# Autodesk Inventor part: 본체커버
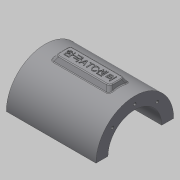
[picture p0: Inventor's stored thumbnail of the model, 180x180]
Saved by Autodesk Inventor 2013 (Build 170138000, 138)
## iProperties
Created: 2015-12
Part Number: 본체커버
Material: 일반
Document SubType Name: Modeling
Designer: mduedu
Density: 2.71 g/cm^3
Mass: 199.348 g
Surface Area: 200.806 cm^2
Volume: 73.5601 cm^3
Author: mduedu
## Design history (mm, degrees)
sketch "스케치1"
  geometry: L1 (45, 40)-(-45, 40); L2 (-45, 40)-(-45, -40); L3 (-45, -40)-(45, -40); L4 (45, -40)-(45, 40); L5 (45, 40)-(-45, -40); L6 (-45, 40)-(45, -40); 1 further point
  constraints: 12 end point, 2 midpoint, 2 parallel, 1 horizontal, 1 perpendicular
  dimensions: "d0" = 90 distance of L2.end L3.end; "d2" = 80 distance of L1.end L2.end
extrude "돌출1" new body sketch "스케치1" distance "d3" = 10; taper "d4" = 0 deg
sketch "스케치2"
  geometry: L1 (0, 40)-(0, -40) reference; C1 r 32.5 at (80, 0); 1 further point
  constraints: 1 centre point
  dimensions: "d5" = 65 diameter of C1; "d6" = 80 distance from line of C1.centre L1
extrude "돌출2" join sketch "스케치2" stored distance "d7" = 75; taper "d8" = 0 deg
sketch "스케치3"
  geometry: L1 (-27.5, -20)-(27.5, -20); L2 (27.5, -20)-(27.5, 20); L3 (27.5, 20)-(-27.5, 20); L4 (-27.5, 20)-(-27.5, -20); L5 (-27.5, -20)-(27.5, 20); L6 (27.5, -20)-(-27.5, 20); 1 further point
  constraints: 12 end point, 2 midpoint, 2 parallel, 1 horizontal, 1 perpendicular
  dimensions: "d9" = 55 distance of L2.end L3.end; "d11" = 40 distance of L1.end L2.end
extrude "돌출3" new body sketch "스케치3" stored distance "d12" = 75; taper "d13" = 0 deg
fillet "모깎기1"
fillet "모깎기2"
feature "결합1"
  node "솔리드2"
fillet "모깎기3" dims "d14" = 10
sketch "스케치4"
  geometry: L1 (-37.5, 47.5)-(37.5, 47.5) reference; L2 (35, 10)-(45, 10) reference; L3 (32.5, 47.5)-(40, 10); L4 (37.5, 47.5)-(37.5, 112.5) reference; L5 (45, 10)-(45, 0) reference; 1 further point
  constraints: 2 end point, 1 midpoint, 1 point on line
  dimensions: "d15" = 5 distance from line of L3.start L4; "d16" = 5 distance from line of L3.end L5
sketch "스케치5"
  geometry: L1 (10, 40)-(10, 30) reference; L2 (10, 35)-(56.569, 22.522); L3 (0, 40)-(10, 40) reference; 2 further points
  constraints: 2 end point, 1 midpoint, 2 other
  dimensions: "d17" = 5 distance from line of L2.start L3; "d18" = 15 deg angle of L2 L3
feature "리브1" dims "d19" = 1, "d20" = 6, "d21" = 0, "d22" = 0, "d23" = 1, "d24" = 1
feature "리브2" dims "d25" = 1, "d26" = 6, "d27" = 0, "d28" = 0, "d29" = 1, "d30" = 1
fillet "모깎기4" dims "d31" = 2
fillet "모깎기5" dims "d32" = 2
fillet "모깎기6" dims "d33" = 2
sketch "스케치6"
  geometry: A1 r 10 centre (-35, 30) between (-35, 40) and (-45, 30) reference; A2 r 10 centre (35, 30) between (45, 30) and (35, 40) reference; A3 r 10 centre (35, -30) between (35, -40) and (45, -30) reference; A4 r 10 centre (-35, -30) between (-45, -30) and (-35, -40) reference; 5 further points
  constraints: 4 coincident
hole "구멍1" sketch "스케치6" at (-35, 30), (35, 30), (35, -30), (-35, -30) diameter "d34" = 7; stored, may be unused: countersink angle "d38" = 90 deg, drill point angle "d40" = 118 deg; dims "d35" = 6, "d36" = 12, "d37" = 3, "d39" = 8
fillet "모깎기7" dims "d41" = 2
hole "구멍2" diameter "d44" = 45; stored, may be unused: countersink angle "d48" = 90 deg, drill point angle "d50" = 118 deg; dims "d42" = 10, "d43" = 10, "d45" = 6, "d46" = 4, "d47" = 2, "d49" = 8
sketch "스케치7" dims "d52" = 26.5
  geometry: L1 (0, 0)-(32.5, 0); L2 (0, 0)-(0, 32.5); A1 r 32.5 centre (0, 0) between (32.5, 0) and (0, 32.5) reference; 3 further points
  constraints: 4 end point, 2 point on circle, 1 coincident, 1 horizontal, 1 point on line, 1 vertical alignment, 2 other
  dimensions: "d51" = 90 deg angle of L2 L1
hole "구멍3" sketch "스케치7" at (0, 26.5) diameter "d54" = 2.459; stored, may be unused: countersink angle "d58" = 90 deg, drill point angle "d60" = 118 deg; dims "d55" = 8, "d56" = 4, "d57" = 2, "d59" = 10
sketch "스케치13"
  geometry: L1 (-45, 80)-(105, 80); L2 (105, 80)-(105, -30); L3 (105, -30)-(-45, -30); L4 (-45, -30)-(-45, 80); L5 (0, 0)-(60, 0) reference; C1 r 32.5 at (30, 80) reference; 1 further point
  constraints: 8 end point, 2 parallel, 1 coincident, 1 horizontal, 1 midpoint, 1 perpendicular
  dimensions: "d99" = 30 distance between parallel lines of L3 L5; "d126" = 150 distance between parallel lines of L2 L4
extrude "돌출8" cut sketch "스케치13" stored distance "d97" = 10; taper "d98" = 0 deg; stored distance "d138" = 10; dims "d2" = 80, "d141" = 1
node "작업 평면4"
  node "작업 평면3"
sketch "스케치19"
  geometry: L1 (-22.5, -6)-(22.5, -6); L2 (22.5, -6)-(22.5, 6); L3 (22.5, 6)-(-22.5, 6); L4 (-22.5, 6)-(-22.5, -6); L5 (-22.5, -6)-(22.5, 6); L6 (22.5, -6)-(-22.5, 6); L7 (-37.5, 32.5)-(-37.5, -32.5) reference; 1 further point
  constraints: 12 end point, 2 midpoint, 2 parallel, 1 horizontal, 1 perpendicular
  dimensions: "d136" = 15 distance between parallel lines of L4 L7; "d137" = 12 distance of L1.end L2.end
extrude "돌출10" join sketch "스케치19" stored distance "d138" = 10; taper "d139" = 30 deg
fillet "모깎기13" dims "d140" = 3
fillet "모깎기14" dims "d141" = 1
fillet "모깎기15" dims "d142" = 1
sketch "스케치20"
  geometry: 2 further points
  constraints: 1 coincident, 1 other
feature "엠보싱2" sketch "스케치20" dims "d0" = 90, "d2" = 80, "d143" = 0.5, "d144" = 0
node "솔리드1"
mirror "대칭1"
mirror "대칭2"
pattern_circular "원형 패턴1" dims angle "d62" = 360 deg
mirror "대칭3"
other parameters: "d135" = 3
